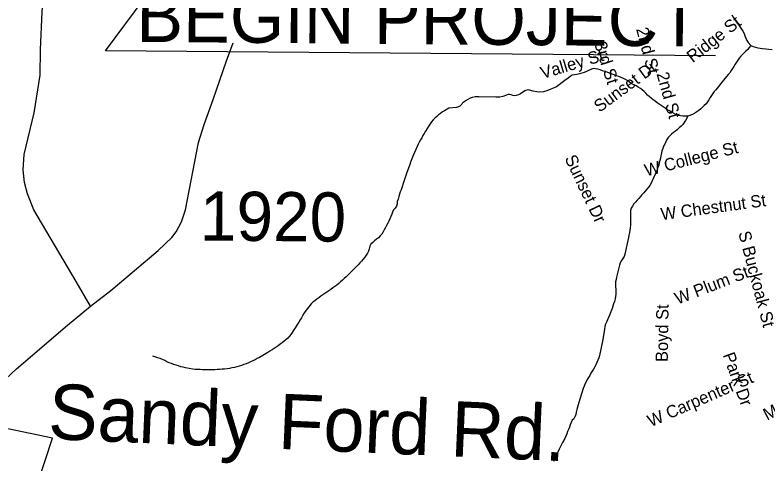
# Model space of a CAD drawing. Extents: x 1379453 to 1387082, y 594364 to 596664.
# Drawn here: x 1380304.5 to 1380505.6, y 596111.6 to 596231.5 of the extents above; entities that cross this region are included whole.
import ezdxf

# ---------------------------------------------------------------- set-up
doc = ezdxf.new("R2010")
doc.units = 0
for name, color, linetype in [('Old_Level_10', 7, 'Continuous'), ('Old_Level_11', 7, 'Continuous'), ('Old_Level_32', 7, 'Continuous'), ('Old_Level_48', 7, 'Continuous'), ('Old_Level_49', 7, 'Continuous'), ('Old_Level_62', 7, 'Continuous'), ('Old_Level_8', 7, 'Continuous')]:
    doc.layers.add(name, color=color, linetype=linetype)

msp = doc.modelspace()

# ---------------------------------------------------------------- linework, layer by layer
at = {"layer": 'Old_Level_11'}
for p, q in [((1380328.61, 596221.97), (1380389.69, 596303.59)), ((1380491.56, 596220.6), (1380328.61, 596221.97))]:
    msp.add_line(p, q, dxfattribs=at)
at = {"layer": 'Old_Level_32'}
for points in [[(1380324.65, 596153.76), (1380320.77, 596160.35), (1380309.47, 596179.5), (1380307.8, 596183.75), (1380307.04, 596186.75), (1380306.64, 596190.16), (1380306.89, 596194.27), (1380309.6, 596205.37), (1380311.17, 596215.39), (1380311.25, 596222.21), (1380311.76, 596232.36), (1380312.24, 596239.51), (1380312.15, 596241.19), (1380311.69, 596242.81), (1380310.92, 596244.65), (1380309.68, 596246.28), (1380307.76, 596248.28), (1380304.79, 596250.29)], [(1380324.65, 596153.76), (1380330.02, 596157.98), (1380342.72, 596168.64), (1380346.31, 596172.06), (1380347.47, 596173.62), (1380348.91, 596176.25), (1380350.04, 596179.44), (1380353.43, 596197.49), (1380354.97, 596202.26), (1380357.4, 596208.93), (1380360.99, 596219.3), (1380362.71, 596224.11)], [(1380263.73, 596113.86), (1380272.14, 596118.56), (1380274.24, 596119.51), (1380294.66, 596128.5), (1380295.83, 596129.38), (1380300.37, 596132.98), (1380304.84, 596137.02), (1380318.44, 596148.73), (1380324.65, 596153.76)]]:
    msp.add_lwpolyline(points, dxfattribs=at)
at = {"layer": 'Old_Level_48'}
msp.add_lwpolyline([(1380302.91, 596083.24), (1380314.44, 596118.5), (1380286.73, 596124.3)], dxfattribs=at)
at = {"layer": 'Old_Level_49'}
msp.add_lwpolyline([(1380302.91, 596083.24), (1380314.44, 596118.5), (1380286.73, 596124.3)], dxfattribs=at)
at = {"layer": 'Old_Level_62'}
for points in [[(1380495.95, 596231.5), (1380496.22, 596230.9), (1380496.6, 596230.36), (1380496.98, 596229.83), (1380497.37, 596229.3), (1380497.75, 596228.77), (1380498.14, 596228.23), (1380498.51, 596227.69), (1380498.86, 596227.14), (1380499.17, 596226.56), (1380499.4, 596225.94), (1380499.63, 596225.32), (1380499.9, 596224.73), (1380500.27, 596224.19), (1380500.99, 596223.33)], [(1380500.99, 596223.33), (1380500.57, 596222.82), (1380500.15, 596222.32), (1380499.69, 596221.86), (1380499.19, 596221.42), (1380498.73, 596220.96), (1380498.29, 596220.47), (1380497.88, 596219.96), (1380497.48, 596219.43), (1380497.11, 596218.9), (1380496.77, 596218.33), (1380496.44, 596217.76), (1380496.11, 596217.19), (1380495.77, 596216.64), (1380495.38, 596216.1), (1380494.93, 596215.63), (1380493.7, 596214.11), (1380491.64, 596211.56), (1380491.23, 596211.05), (1380490.83, 596210.53), (1380490.44, 596210), (1380490.1, 596209.44), (1380489.77, 596208.86), (1380489.42, 596208.31), (1380489.01, 596207.8), (1380488.56, 596207.32), (1380488.09, 596206.87), (1380487.6, 596206.42), (1380487.08, 596206), (1380486.56, 596205.61), (1380486.02, 596205.25), (1380485.43, 596204.97), (1380484.18, 596204.51)], [(1380500.99, 596223.33), (1380501.62, 596223.12), (1380502.24, 596222.91), (1380502.87, 596222.73), (1380504.13, 596222.52), (1380506.71, 596222.27)], [(1380484.18, 596204.51), (1380483.52, 596204.51), (1380482.86, 596204.52), (1380482.21, 596204.56), (1380481.57, 596204.7), (1380480.95, 596204.95), (1380480.37, 596205.25), (1380479.79, 596205.56), (1380479.22, 596205.88), (1380478.65, 596206.22), (1380478.1, 596206.58), (1380477.56, 596206.94), (1380477.02, 596207.32), (1380476.49, 596207.7), (1380475.95, 596208.08), (1380475.43, 596208.47), (1380474.9, 596208.87), (1380474.38, 596209.28), (1380473.88, 596209.69), (1380473.39, 596210.13), (1380472.93, 596210.6), (1380472.46, 596211.07), (1380471.98, 596211.51), (1380471.47, 596211.91), (1380470.91, 596212.25), (1380470.32, 596212.55), (1380469.73, 596212.85), (1380469.16, 596213.16), (1380468.62, 596213.55), (1380468.1, 596213.95), (1380467.53, 596214.27), (1380466.93, 596214.54), (1380466.33, 596214.8), (1380465.72, 596215.04), (1380465.1, 596215.28), (1380464.49, 596215.52), (1380463.26, 596215.98), (1380462.65, 596216.2), (1380462.03, 596216.42), (1380461.4, 596216.63), (1380460.78, 596216.83), (1380460.14, 596217.01), (1380459.51, 596217.16), (1380458.86, 596217.2), (1380458.23, 596216.97), (1380457.65, 596216.69), (1380457.05, 596216.4), (1380456.44, 596216.16), (1380455.82, 596215.96), (1380455.18, 596215.79), (1380454.55, 596215.64), (1380453.91, 596215.5), (1380453.28, 596215.39), (1380452.72, 596215.05), (1380452.17, 596214.67), (1380451.34, 596213.97)], [(1380451.34, 596213.97), (1380449.11, 596212.28), (1380446.53, 596211.26), (1380445.64, 596211.01), (1380444.55, 596210.9), (1380443.81, 596210.95), (1380442.85, 596211.19), (1380441.87, 596211.45), (1380441.54, 596211.48), (1380441.12, 596211.46), (1380440.59, 596211.24), (1380439.49, 596210.44), (1380438.94, 596210.16), (1380438.3, 596209.98), (1380437.77, 596209.93), (1380437.41, 596209.98), (1380436.96, 596210.14), (1380436.5, 596210.24), (1380436.16, 596210.26), (1380435.76, 596210.12), (1380434.72, 596209.76), (1380433.92, 596209.57), (1380432.91, 596209.56), (1380428.33, 596209.67), (1380427.32, 596209.62), (1380426.56, 596209.5), (1380426.05, 596209.33), (1380425.43, 596208.97), (1380424.76, 596208.56), (1380424.29, 596208.26), (1380424.01, 596208.02), (1380423.76, 596207.73), (1380423.59, 596207.47), (1380423.29, 596207.18), (1380422.9, 596206.96), (1380422.35, 596206.77), (1380420.34, 596206.62)], [(1380420.34, 596206.62), (1380419.2, 596205.95), (1380418.64, 596205.61), (1380418.1, 596205.24), (1380417.59, 596204.83), (1380417.09, 596204.4), (1380416.61, 596203.95), (1380416.16, 596203.47), (1380415.73, 596202.98), (1380415.34, 596202.45), (1380414.97, 596201.91), (1380414.05, 596200.45), (1380413.73, 596199.87), (1380413.41, 596199.3), (1380413.08, 596198.73), (1380412.76, 596198.16), (1380412.44, 596197.58), (1380412.13, 596197), (1380411.83, 596196.42), (1380410.8, 596194.01), (1380410.11, 596192.19), (1380409.88, 596191.58), (1380409.02, 596189.18), (1380408.41, 596187.3), (1380407.61, 596184.86), (1380407.36, 596184.25), (1380407.14, 596183.63), (1380406.94, 596183), (1380406.75, 596182.37), (1380406.57, 596181.74), (1380406.49, 596181.11), (1380406.33, 596180.5), (1380406.03, 596179.9), (1380405.59, 596179.48), (1380405.3, 596178.89), (1380405.07, 596178.28), (1380404.83, 596177.67), (1380404.58, 596177.06), (1380404.29, 596176.47), (1380404, 596175.88), (1380403.7, 596175.3), (1380403.39, 596174.72), (1380403.08, 596174.14), (1380402.75, 596173.57), (1380402.41, 596173.01), (1380401.99, 596172.5), (1380401.52, 596172.05), (1380401.02, 596171.62), (1380400.51, 596171.2), (1380400.01, 596170.78), (1380399.53, 596170.34), (1380399.25, 596169.75), (1380399.09, 596169.1), (1380398.89, 596168.48), (1380398.6, 596167.89), (1380398.25, 596167.34), (1380397.86, 596166.8), (1380397.45, 596166.29), (1380397.02, 596165.8), (1380396.57, 596165.31), (1380396.12, 596164.84), (1380395.66, 596164.37), (1380393.8, 596162.51), (1380393.33, 596162.05), (1380392.87, 596161.59), (1380392.39, 596161.13), (1380391.91, 596160.68), (1380391.42, 596160.25), (1380390.92, 596159.82), (1380390.41, 596159.41), (1380389.9, 596159.01), (1380389.37, 596158.62), (1380388.83, 596158.25), (1380388.29, 596157.87), (1380387.75, 596157.5), (1380387.2, 596157.13), (1380386.66, 596156.76), (1380386.12, 596156.39), (1380385.59, 596156.01), (1380385.05, 596155.62), (1380384.53, 596155.22), (1380384.02, 596154.81), (1380383.55, 596154.35), (1380381.95, 596152.34), (1380381.61, 596151.78), (1380381.28, 596151.21), (1380380.95, 596150.64), (1380380.62, 596150.07), (1380380.27, 596149.51), (1380379.93, 596148.95), (1380378.15, 596146.24), (1380377.75, 596145.73), (1380377.3, 596145.26), (1380376.82, 596144.81), (1380376.31, 596144.39), (1380375.79, 596143.98), (1380375.27, 596143.58), (1380374.74, 596143.19), (1380374.2, 596142.81), (1380373.66, 596142.44)], [(1380484.18, 596204.51), (1380483.51, 596203.36), (1380483.17, 596202.8), (1380482.79, 596202.27), (1380482.35, 596201.79), (1380481.87, 596201.35), (1380481.37, 596200.92), (1380480.85, 596200.51), (1380480.33, 596200.1), (1380479.82, 596199.68), (1380479.33, 596199.25), (1380478.86, 596198.8), (1380478.51, 596198.24), (1380478.24, 596197.65), (1380477.97, 596197.05), (1380477.7, 596196.44), (1380477.46, 596195.83), (1380477.24, 596195.22), (1380477.08, 596194.58), (1380476.96, 596193.94), (1380476.85, 596193.29), (1380476.71, 596192.65), (1380476.54, 596192.01), (1380476.37, 596191.38), (1380476.16, 596190.75), (1380475.93, 596190.14), (1380474.65, 596187.18), (1380474.34, 596186.59), (1380474.01, 596186.02), (1380473.64, 596185.49), (1380473.22, 596184.98), (1380472.8, 596184.48), (1380472.36, 596183.99), (1380471.91, 596183.5), (1380471.47, 596183.02), (1380471.03, 596182.53), (1380470.59, 596182.04), (1380470.16, 596181.55), (1380469.75, 596181.04), (1380469.38, 596180.49), (1380469.06, 596179.92), (1380468.88, 596179.29), (1380468.86, 596178.63), (1380468.87, 596177.98), (1380468.88, 596177.32), (1380468.87, 596176.66), (1380468.85, 596176), (1380468.83, 596175.35), (1380468.76, 596174.69), (1380468.66, 596174.05), (1380468.54, 596173.4), (1380468.41, 596172.76), (1380468.28, 596172.12), (1380467.32, 596167.62), (1380467.11, 596167.04), (1380466.76, 596166.48), (1380466.42, 596165.92), (1380466.12, 596165.34), (1380465.92, 596164.71), (1380465.14, 596161.53), (1380464.99, 596160.89), (1380464.88, 596160.24), (1380464.84, 596159.59), (1380464.87, 596158.93), (1380464.92, 596158.27), (1380464.96, 596157.61), (1380464.96, 596156.96), (1380464.86, 596156.32), (1380464.72, 596155.68), (1380464.54, 596155.05), (1380464.34, 596154.42), (1380464.13, 596153.8), (1380463.91, 596153.18), (1380463.23, 596151.32), (1380462.97, 596150.71), (1380462.68, 596150.12), (1380462.4, 596149.53), (1380462.15, 596148.92), (1380461.99, 596148.29), (1380461.89, 596147.64), (1380461.83, 596146.99), (1380461.41, 596144.4), (1380460.53, 596140.57), (1380460.35, 596139.94), (1380460.11, 596139.33), (1380459.86, 596138.72), (1380459.58, 596138.13), (1380459.29, 596137.54), (1380458.98, 596136.96), (1380458.64, 596136.4), (1380458.29, 596135.84), (1380457.94, 596135.29), (1380457.61, 596134.72), (1380457.28, 596134.15), (1380456.97, 596133.57), (1380456.69, 596132.98), (1380456.45, 596132.37), (1380456.24, 596131.75), (1380455.03, 596128), (1380454.49, 596126.14)], [(1380373.66, 596142.44), (1380373.11, 596142.08), (1380372.55, 596141.73), (1380371.99, 596141.41), (1380369.72, 596140.08), (1380369.14, 596139.77), (1380368.57, 596139.47), (1380367.98, 596139.18), (1380367.38, 596138.9), (1380366.78, 596138.64), (1380366.17, 596138.4), (1380365.55, 596138.17), (1380364.93, 596137.96), (1380364.3, 596137.76), (1380363.68, 596137.58), (1380363.04, 596137.4), (1380362.4, 596137.27), (1380361.75, 596137.16), (1380361.1, 596137.06), (1380360.45, 596136.98), (1380359.79, 596136.92), (1380359.14, 596136.86), (1380358.48, 596136.82), (1380357.83, 596136.8), (1380357.17, 596136.78), (1380356.51, 596136.78), (1380355.86, 596136.78), (1380355.2, 596136.79), (1380354.54, 596136.8), (1380353.89, 596136.81), (1380353.23, 596136.84), (1380352.57, 596136.89), (1380351.93, 596136.98), (1380350.01, 596137.3), (1380349.37, 596137.44), (1380348.73, 596137.61), (1380348.11, 596137.8), (1380347.48, 596138), (1380346.85, 596138.2), (1380346.24, 596138.42), (1380345.62, 596138.66), (1380345.03, 596138.94), (1380344.47, 596139.28), (1380343.87, 596139.55), (1380343.25, 596139.77), (1380342.63, 596139.98), (1380341.27, 596140.43)], [(1380454.49, 596126.14), (1380454.36, 596125.49), (1380454.2, 596124.85), (1380453.97, 596124.22), (1380453.69, 596123.64), (1380453.29, 596123.3), (1380453.01, 596122.71), (1380452.76, 596122.1), (1380452.52, 596121.49), (1380452.29, 596120.87), (1380452.05, 596120.26), (1380451.81, 596119.65), (1380451.57, 596119.04), (1380451.33, 596118.43), (1380450.69, 596117.34), (1380449.79, 596115.59), (1380449, 596113.8), (1380448.71, 596113.21), (1380448.26, 596112.31)]]:
    msp.add_lwpolyline(points, dxfattribs=at)

# ---------------------------------------------------------------- texts
at = {"layer": 'Old_Level_10'}
for s, height, rotation, p in [('Ridge St', 3.281, 38.1143, (1380485.45, 596218.61)), ('2nd St', 3.281, 284.7739, (1380470.31, 596227.75)), ('3rd St', 3.281, 287.8528, (1380459.13, 596223.83)), ('Valley St', 3.281, 16.5952, (1380445.36, 596214.4)), ('Sunset Dr', 3.281, 36.573, (1380460.59, 596205.36)), ('2nd St', 3.281, 285.5895, (1380475.76, 596215.79)), ('W College St', 3.2808, 14.398, (1380473.07, 596188.37)), ('Sunset Dr', 3.281, 295.3782, (1380451.18, 596193.23)), ('W Chestnut St', 3.2808, 7.7516, (1380477.16, 596176.69)), ('S Buckoak St', 3.2808, 284.7599, (1380497.6, 596173.35)), ('W Plum St', 3.281, 21.0636, (1380481.41, 596154.14)), ('Boyd St', 3.281, 89.1517, (1380478.8, 596138.85)), ('Park Dr', 3.281, 289.7742, (1380493.44, 596140.75)), ('W Carpenter St', 3.2808, 23.5483, (1380474.26, 596121.43)), ('Moore St', 3.281, 27.1655, (1380505.31, 596123.15))]:
    msp.add_text(s, height=height, rotation=rotation, dxfattribs=at).set_placement(p)
at = {"layer": 'Old_Level_11'}
for s, height, rotation, p in [('BEGIN PROJECT', 14, 359.52, (1380336.82, 596224.34)), ('Sandy Ford Rd.', 14.7638, 357.5238, (1380313.14, 596118.34))]:
    msp.add_text(s, height=height, rotation=rotation, dxfattribs=at).set_placement(p)
at = {"layer": 'Old_Level_8'}
msp.add_text('1920', height=13.123, rotation=359.52, dxfattribs=at).set_placement((1380353.81, 596171.3))

doc.saveas('drawing.dxf')
